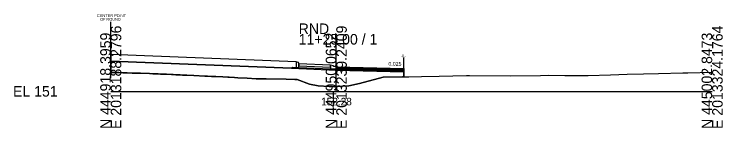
# Model space of a CAD drawing. Extents: x -26 to 163, y -10 to 7518.
# Drawn here: x -25.7 to 162.8, y 2490.3 to 2520.5 of the extents above; entities that cross this region are included whole.
import ezdxf

# ---------------------------------------------------------------- set-up
doc = ezdxf.new("R2010")
doc.units = 0
for name, color, linetype in [('Exist Cross Section Cell', 7, 'Continuous'), ('Exist XS Center Line Elevation Label', 7, 'Continuous'), ('Exist XS Ground Line', 7, 'Continuous'), ('Prop CMT Conc Surface', 7, 'Continuous'), ('Prop CMT Concrete Structures', 7, 'Continuous'), ('Prop CMT Pvmt Course 1', 7, 'Continuous'), ('Prop CMT Pvmt Course 1 CG', 7, 'Continuous'), ('Prop CMT Pvmt Course 2', 7, 'Continuous'), ('Prop CMT Pvmt Course 3', 7, 'Continuous'), ('Prop CMT Pvmt Surface', 7, 'Continuous'), ('Prop CMT Shear Line', 7, 'Continuous'), ('Prop CMT Shear Line Text', 7, 'Continuous'), ('Prop CMT Slope Grass', 7, 'Continuous'), ('Prop CMT Subgrade Earthwork', 7, 'Continuous'), ('Prop XS Earthwork Shape', 7, 'Continuous'), ('Prop XS SE Text', 7, 'Continuous')]:
    doc.layers.add(name, color=color, linetype=linetype)

msp = doc.modelspace()

# ---------------------------------------------------------------- linework, layer by layer
at = {"layer": 'Exist Cross Section Cell'}
for p, q in [((60, 2500), (60, 2515.25)), ((0, 2500), (60, 2500)), ((60, 2500), (160, 2500))]:
    msp.add_line(p, q, dxfattribs=at)
at = {"layer": 'Exist XS Ground Line'}
msp.add_lwpolyline([(0, 2505.05), (0.31, 2505.05), (1.46, 2505.02), (2.12, 2505), (3.2, 2504.97), (3.94, 2504.94), (4.39, 2504.92), (5.74, 2504.88), (7.56, 2504.81), (7.93, 2504.8), (10.27, 2504.72), (11.19, 2504.69), (12.64, 2504.64), (13.24, 2504.61), (14.82, 2504.53), (16.18, 2504.47), (16.65, 2504.44), (17.35, 2504.41), (18.44, 2504.37), (19.11, 2504.33), (20.25, 2504.28), (22.07, 2504.2), (25.01, 2504.07), (25.7, 2504.04), (26.8, 2503.99), (27.97, 2503.93), (29.83, 2503.83), (31.13, 2503.76), (31.54, 2503.74), (32.95, 2503.67), (33.81, 2503.63), (36.3, 2503.5), (38.66, 2503.37), (39.69, 2503.31), (40.17, 2503.3), (41.35, 2503.3), (46.66, 2503.27), (48.94, 2503.17), (49.64, 2503.15), (52.91, 2501.95), (55.17, 2501.5), (58.12, 2501.31), (59.42, 2501.23), (60.08, 2501.28), (63.33, 2501.47), (66.15, 2502.1), (72.45, 2503.77), (77.62, 2503.9), (79.26, 2503.89), (82.65, 2503.95), (87.36, 2504.04), (94.65, 2504.19), (95.4, 2504.19), (106.41, 2504.12), (114.34, 2504.23), (116.54, 2504.28), (120.83, 2504.22), (126.99, 2504.19), (132.95, 2504.36), (137.42, 2504.53), (141.74, 2504.65), (145.76, 2504.78), (152.24, 2504.9), (153.03, 2504.93), (153.51, 2504.93), (160, 2505.08)], dxfattribs=at)
at = {"layer": 'Prop CMT Conc Surface'}
for points in [[(50, 2507.53), (49.96, 2507.63), (49.85, 2507.67), (49.34, 2507.86)], [(50, 2507.36), (50, 2507.53)], [(60, 2506.56), (59.25, 2506.58), (59.25, 2506.75), (58.5, 2507)]]:
    msp.add_lwpolyline(points, dxfattribs=at)
at = {"layer": 'Prop CMT Concrete Structures'}
for points in [[(50, 2507.53), (49.96, 2507.63), (49.85, 2507.67), (49.34, 2507.86)], [(49.34, 2507.86), (49.34, 2506.36)], [(50, 2507.36), (50, 2507.53)], [(49.34, 2506.36), (50, 2506.36)], [(50, 2506.36), (50, 2507.36)], [(50, 2507.36), (50, 2506.78)], [(58.5, 2507), (50, 2507.34)], [(50, 2506.76), (58.5, 2506.42)], [(60, 2506.56), (59.25, 2506.58), (59.25, 2506.75), (58.5, 2507)], [(58.5, 2507), (58.5, 2506.02)], [(58.5, 2506.42), (58.5, 2507)], [(58.5, 2506.02), (60, 2505.98)], [(60, 2505.98), (60, 2506.56)]]:
    msp.add_lwpolyline(points, dxfattribs=at)
at = {"layer": 'Prop CMT Pvmt Course 1'}
for points in [[(60, 2506.56), (78, 2506.11)], [(60, 2506.31), (60, 2506.56)], [(78, 2505.86), (60, 2506.31)], [(78, 2506.11), (78, 2505.86)]]:
    msp.add_lwpolyline(points, dxfattribs=at)
msp.add_lwpolyline([(60, 2506.31), (60, 2506.44), (60, 2506.44), (60, 2506.31)], close=True, dxfattribs=at)
at = {"layer": 'Prop CMT Pvmt Course 1 CG'}
for points in [[(60, 2505.65), (60, 2505.98)], [(78, 2505.2), (78, 2505.53)]]:
    msp.add_lwpolyline(points, dxfattribs=at)
at = {"layer": 'Prop CMT Pvmt Course 2'}
for points in [[(60, 2505.98), (60, 2506.31)], [(60, 2506.31), (78, 2505.86)], [(78, 2505.53), (60, 2505.98)], [(78, 2505.86), (78, 2505.53)]]:
    msp.add_lwpolyline(points, dxfattribs=at)
at = {"layer": 'Prop CMT Pvmt Course 3'}
for points in [[(50, 2506.36), (58.5, 2506.02)], [(60, 2505.98), (78, 2505.53)], [(60, 2505.65), (60, 2505.98)], [(78, 2505.2), (60, 2505.65)], [(78, 2505.53), (78, 2505.2)]]:
    msp.add_lwpolyline(points, dxfattribs=at)
at = {"layer": 'Prop CMT Pvmt Surface'}
msp.add_lwpolyline([(60, 2506.56), (78, 2506.11)], dxfattribs=at)
at = {"layer": 'Prop CMT Shear Line'}
for p, q in [((0, 2503.51), (0, 2518.51)), ((78, 2503.94), (78, 2508.95))]:
    msp.add_line(p, q, dxfattribs=at)
at = {"layer": 'Prop CMT Slope Grass'}
for p, q in [((49.34, 2507.84), (0, 2509.82)), ((48.06, 2506.13), (0, 2508.05))]:
    msp.add_line(p, q, dxfattribs=at)
at = {"layer": 'Prop CMT Subgrade Earthwork'}
for p, q in [((0, 2509.82), (0, 2505.05)), ((48.34, 2506.4), (48.06, 2506.13)), ((78, 2506.11), (78, 2505.2)), ((78, 2505.2), (78, 2503.9))]:
    msp.add_line(p, q, dxfattribs=at)
for points in [[(48.06, 2506.13), (60, 2505.65)], [(48.34, 2506.4), (49.34, 2506.36)], [(60, 2505.65), (78, 2505.2)]]:
    msp.add_lwpolyline(points, dxfattribs=at)
at = {"layer": 'Prop XS Earthwork Shape'}
msp.add_lwpolyline([(48.06, 2506.13), (60, 2505.65), (78, 2505.2), (78, 2503.9), (77.62, 2503.9), (72.45, 2503.77), (66.15, 2502.1), (63.33, 2501.47), (60.08, 2501.28), (59.42, 2501.23), (58.12, 2501.31), (55.17, 2501.5), (52.91, 2501.95), (49.64, 2503.15), (48.94, 2503.17), (46.66, 2503.27), (41.35, 2503.3), (40.17, 2503.3), (39.69, 2503.31), (38.66, 2503.37), (36.3, 2503.5), (33.81, 2503.63), (32.95, 2503.67), (31.54, 2503.74), (31.13, 2503.76), (29.83, 2503.83), (27.97, 2503.93), (26.8, 2503.99), (25.7, 2504.04), (25.01, 2504.07), (22.07, 2504.2), (20.25, 2504.28), (19.11, 2504.33), (18.44, 2504.37), (17.35, 2504.41), (16.65, 2504.44), (16.18, 2504.47), (14.82, 2504.53), (13.24, 2504.61), (12.64, 2504.64), (11.19, 2504.69), (10.27, 2504.72), (7.93, 2504.8), (7.56, 2504.81), (5.74, 2504.88), (4.39, 2504.92), (3.94, 2504.94), (3.2, 2504.97), (2.12, 2505), (1.46, 2505.02), (0.31, 2505.05), (0, 2505.05), (0, 2508.05)], close=True, dxfattribs=at)

# ---------------------------------------------------------------- texts
at = {"layer": 'Exist Cross Section Cell'}
for s, p in [('E 2013188.2796', (2.8, 2490)), ('E 2013239.2409', (62.8, 2490)), ('E 2013324.1764', (162.8, 2490)), ('N 444918.3959', (0, 2490)), ('N 444950.0652', (60, 2490)), ('N 445002.8473', (160, 2490))]:
    msp.add_text(s, height=2.8, rotation=90, dxfattribs=at).set_placement(p)
for s, p in [('RND', (50, 2515.25)), ('11+25.00 / 1', (50, 2512.45)), ('EL 151', (-26, 2498.6))]:
    msp.add_text(s, height=2.8, dxfattribs=at).set_placement(p)
at = {"layer": 'Exist XS Center Line Elevation Label'}
msp.add_text('152.28', height=2, dxfattribs=at).set_placement((55.96, 2496.28))
at = {"layer": 'Prop CMT Shear Line Text'}
for s, p in [('CENTER POINT', (-3.64, 2519.76)), ('OF ROUND', (-2.88, 2518.78)), ('-L-', (77.27, 2509.07))]:
    msp.add_text(s, height=0.75, dxfattribs=at).set_placement(p)
at = {"layer": 'Prop XS SE Text'}
msp.add_text('0.025', height=1, rotation=358.5613, dxfattribs=at).set_placement((73.87, 2506.84))

doc.saveas('drawing.dxf')
